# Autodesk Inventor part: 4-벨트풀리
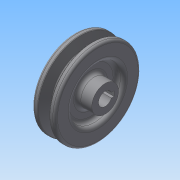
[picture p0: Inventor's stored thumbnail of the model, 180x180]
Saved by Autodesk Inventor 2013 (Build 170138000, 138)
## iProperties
Created: 2015-02
Part Number: 4-벨트풀리
Material: 일반
Document SubType Name: Modeling
Designer: Administrator
Density: 1 g/cm^3
Author: Administrator
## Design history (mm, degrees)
sketch "스케치1"
  geometry: L1 (0, 0)-(25, 0); L2 (25, 0)-(25, 11); L3 (25, 11)-(13, 11); L4 (13, 11)-(13, 21.5); L5 (13, 21.5)-(19, 21.5); L6 (19, 21.5)-(19, 35.2); L7 (19, 35.2)-(14.325, 35.2); L8 (14.325, 35.2)-(11.574, 26.2); L9 (11.574, 26.2)-(7.426, 26.2); L10 (7.426, 26.2)-(4.675, 35.2); L11 (4.675, 35.2)-(0, 35.2); L12 (0, 35.2)-(0, 21.5); L13 (0, 21.5)-(6, 21.5); L14 (6, 21.5)-(6, 11); L15 (6, 11)-(0, 11); L16 (0, 11)-(0, 0); 2 further points
  constraints: 32 end point, 10 parallel, 5 equal length, 2 collinear, 2 perpendicular, 2 point on line, 1 horizontal, 1 horizontal alignment, 1 vertical alignment
  dimensions: "d0" = 25 distance of L1.start L1.end; "d1" = 19 distance between parallel lines of L6 L12; "d2" = 6 distance of L12.end L13.end; "d3" = 2.7 distance from line of point (5.5, 32.5) L11; "d4" = 6.3 distance from line of L9 point (13.5, 32.5); "d5" = 34 deg angle of L8 L10; "d6" = 8 distance of point (13.5, 32.5) point (5.5, 32.5); "d7" = 22 diameter of L3 L1; "d8" = 43 diameter of L5 L1; "d9" = 65 diameter of point (13.5, 32.5) L1
revolve "회전1" sketch "스케치1" stored, may be unused: angle "d10" = 90 deg
sketch "스케치2"
  geometry: L1 (-2, 5.123)-(-2, 7.3); L2 (-2, 7.3)-(2, 7.3); L3 (2, 7.3)-(2, 5.123); C1 r 11 at (0, 0) reference; A1 r 5.5 centre (0, 0) between (-2, 5.123) and (2, 5.123)
  constraints: 6 end point, 2 parallel, 2 point on circle, 1 centre point, 1 coincident, 1 perpendicular, 1 vertical
  dimensions: "d11" = 11 diameter of A1; "d13" = 4 distance of L1.end L2.end; "d14" = 12.8 dimension on A1 L2
extrude "돌출1" cut sketch "스케치2" stored distance "d15" = 10; taper "d16" = 0 deg
fillet "모깎기1" dims "d17" = 2, "d18" = 0.5, "d19" = 1
fillet "모깎기2" dims "d20" = 3
node "솔리드1"
